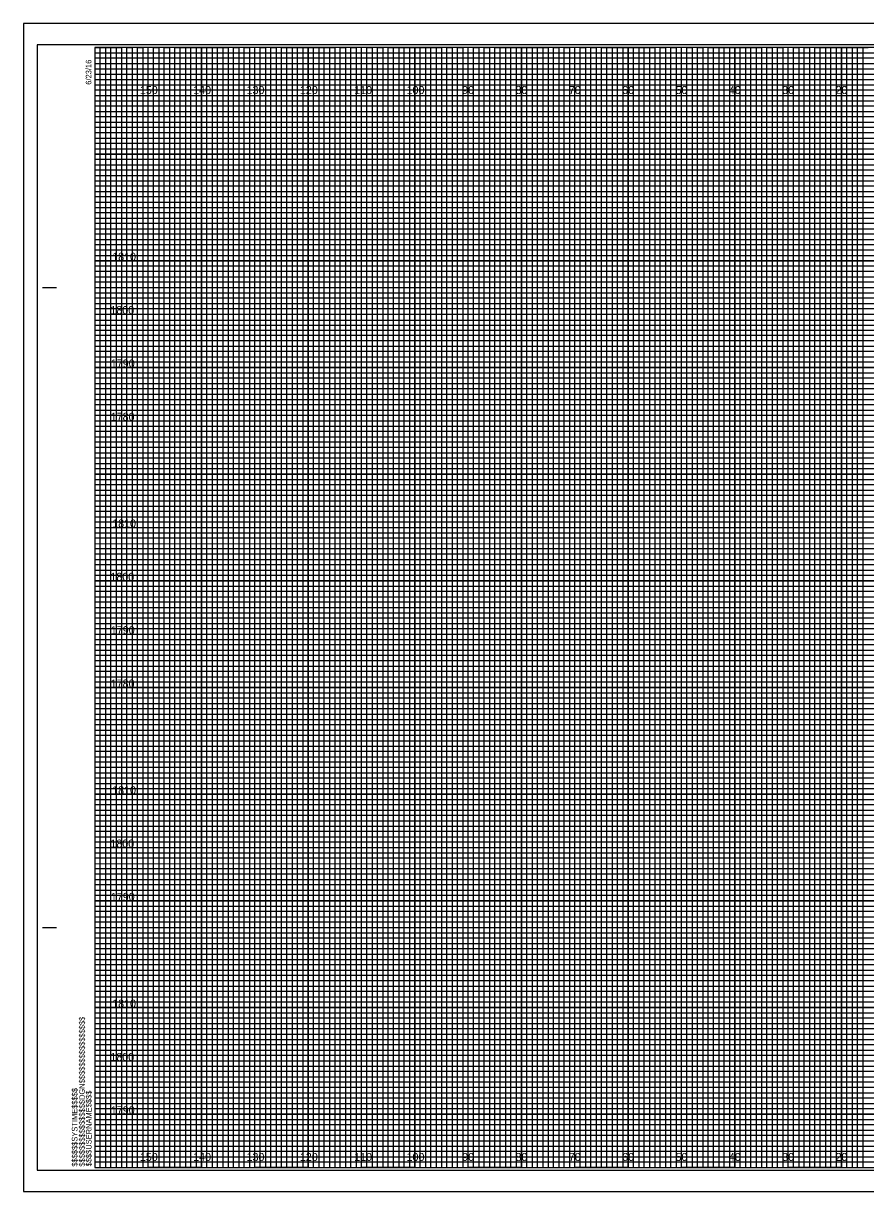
# Model space of a CAD drawing. Extents: x -13 to 323, y -5 to 434.
# Drawn here: x -13.4 to 144.5, y -4.5 to 214.5 of the extents above; entities that cross this region are included whole.
import ezdxf

# ---------------------------------------------------------------- set-up
doc = ezdxf.new("R2010")
doc.units = 0
for name, color, linetype in [('Old_Level_62', 7, 'Continuous'), ('Pattern 1', 7, 'Continuous'), ('Pattern 4', 7, 'Continuous'), ('Pattern 5', 7, 'Continuous'), ('Prop Dimension', 7, 'Continuous'), ('Prop Horizontal Alignment', 7, 'Continuous'), ('Prop PHM Label Text', 7, 'Continuous'), ('Scratch_Level_0', 7, 'Continuous'), ('Scratch_Level_2', 7, 'Continuous'), ('Scratch_Level_3', 7, 'Continuous'), ('Scratch_Level_5', 7, 'Continuous')]:
    doc.layers.add(name, color=color, linetype=linetype)

msp = doc.modelspace()

# ---------------------------------------------------------------- linework, layer by layer
at = {"layer": 'Old_Level_62'}
for p, q in [((0, 209), (260, 209)), ((260, 207.98), (0, 207.98)), ((0, 207.98), (0, 207)), ((0, 207), (260, 207)), ((260, 205.89), (0, 205.89)), ((0, 205.89), (0, 204)), ((0, 204), (320, 204))]:
    msp.add_line(p, q, dxfattribs=at)
for points in [[(0, 203), (270, 203), (320, 203), (320, 202), (0, 202)], [(0, 201), (320, 201), (320, 199), (0, 199)], [(0, 198), (320, 198), (320, 197), (0, 196.98)], [(0, 196), (320, 196), (320, 194), (0, 194)], [(0, 193), (320, 193), (320, 192), (0, 192)], [(0, 191), (320, 191), (320, 189), (0, 189)], [(0, 188), (320, 188), (320, 187), (0, 187)], [(0, 186), (320, 186), (320, 184), (0, 184)], [(0, 183), (320, 183), (320, 182), (0, 182)], [(0, 181), (320, 181), (320, 179), (0, 179)], [(0, 178), (320, 178), (320, 177), (0, 177)], [(0, 176), (320, 176), (320, 173.95), (320, 173), (320, 172), (0, 172)], [(0, 174), (320, 174), (320, 173), (0, 173)], [(0, 171), (320, 171), (320, 169), (0, 169.03)], [(0, 169.03), (320, 169), (320, 168), (0, 168)], [(0, 167), (320, 167), (320, 166), (0, 166)], [(0, 164), (320, 164), (320, 163), (0, 163)], [(0, 162), (320, 162), (320, 161), (0, 161)], [(-0.07, 158.89), (320, 158.89), (320, 157.88), (-0.07, 157.88)], [(0, 157), (320, 157), (320, 156), (0, 156)], [(0, 154), (320, 154), (320, 153), (0, 153)], [(0, 152), (320, 152), (320, 151), (0, 151)], [(0, 149), (320, 149), (320, 148), (0, 148)], [(0, 147), (320, 147), (320, 146), (0, 146)], [(0, 144), (320, 144), (320, 143), (0, 143)], [(0, 142), (320, 142), (320, 141), (0, 141)], [(0, 139), (320, 139), (319.99, 137.98), (0, 138)], [(0, 137), (320, 137), (320, 136), (0, 136)], [(0, 134), (320, 134), (320, 133), (0, 133)], [(0, 132), (320, 132), (320, 131), (0, 131)], [(0, 129), (320, 129), (320, 128), (0, 128)], [(0, 127), (320, 127), (320, 126), (0, 126)], [(0, 124), (320, 124), (320, 123), (0, 123)], [(0, 122), (320, 122), (320, 121), (0, 121)], [(0, 119), (320, 119), (320, 118), (0, 118)], [(0, 116.99), (320.07, 116.91), (320, 116), (0, 116)], [(0, 114), (320, 114), (320, 113), (0, 113)], [(0, 112), (320, 112), (320, 111), (0, 111)], [(0, 109), (320, 109), (320, 108), (0, 108)], [(0, 107), (320, 107), (320, 106), (0, 106)], [(0, 104), (320, 104), (320, 103), (0, 103)], [(0, 102), (320, 102), (320, 101), (0, 101)], [(0, 99), (320, 99), (320, 98), (0, 98)], [(0, 97), (320, 97), (320, 96), (0, 96)], [(0, 94), (320, 94), (320, 93), (0, 93)], [(0, 92), (320, 92), (320, 91), (0, 91)], [(0, 89), (320, 89), (320, 88), (0, 88)], [(0, 87), (320, 87), (320, 86), (0, 86)], [(0, 84), (320, 84), (320, 83), (0, 83)], [(0, 82), (320, 82), (320, 81), (0, 81)], [(0, 79), (320, 79), (319.99, 77.98), (0, 78)], [(0, 77), (320, 77), (320, 76), (0, 76)], [(0, 74), (320, 74), (320, 73), (0, 73)], [(0, 72), (320, 72), (320, 71), (0, 71)], [(0, 69), (320, 69), (320, 68), (0, 68)], [(0, 67), (320, 67), (320, 66), (0, 66)], [(0, 64), (320, 64), (320, 63), (0, 63)], [(0, 62), (320, 62), (320, 61), (0, 61)], [(0, 59), (320, 59), (320, 58), (0, 58)], [(0, 56.99), (320.07, 56.91), (320, 56), (0, 56)], [(0, 54), (320, 54), (320, 53), (0, 53)], [(0, 52), (320, 52), (320, 51), (0, 51)], [(0, 49), (320, 49), (320, 48), (0, 48)], [(0, 47), (320, 47), (320, 46), (0, 46)], [(0, 44), (320, 44), (320, 43), (0, 43)], [(0, 42), (320, 42), (320, 41), (0, 41)], [(0, 39), (320, 39), (320, 38), (0, 38)], [(0, 37), (320, 37), (320, 36), (0, 36)], [(0, 34), (320, 34), (320, 33), (0, 33)], [(0, 32), (320, 32), (320, 31), (0, 31)], [(0, 29), (320, 29), (320, 28), (0, 28)], [(0, 27), (320, 27), (320, 26), (0, 26)], [(0, 24), (320, 24), (320, 23), (0, 23)], [(0, 22), (320, 22), (320, 21), (0, 21)], [(0, 19), (320, 19), (320, 18), (0, 18)], [(0, 17), (320, 17), (320, 16), (0, 16)], [(0, 14), (320, 14), (320, 13), (0, 13)], [(0, 12), (320, 12), (320, 11), (0, 11)], [(0, 9), (320, 9), (320, 8), (0, 8)], [(0, 7), (320, 7), (320, 6), (0, 6)], [(0, 4), (320, 4), (320, 3), (0, 3)], [(0, 2), (320, 2), (320, 1), (0, 1)]]:
    msp.add_lwpolyline(points, dxfattribs=at)
at = {"layer": 'Pattern 1'}
for p, q in [((323.3, 214.5), (-13.4, 214.5)), ((-13.4, 214.5), (-13.4, -4.5)), ((-13.4, -4.5), (323.3, -4.5))]:
    msp.add_line(p, q, dxfattribs=at)
at = {"layer": 'Pattern 4'}
for points in [[(0, 210), (5, 210), (5, 0), (15, 0), (15, 210), (25, 210), (25, 0), (35, 0), (35, 210), (45, 210), (45, 0), (55, 0), (55, 210), (65, 210), (65, 0), (75, 0), (75, 210), (85, 210), (85, 0), (95, 0), (95, 210), (105, 210), (105, 0), (115, 0), (115, 210), (125, 210), (125, 0), (135, 0), (135, 210), (145, 210)], [(0, 205), (275, 205)], [(0, 185), (320, 185), (320, 195), (0, 195)], [(0, 165), (320, 165), (320, 175), (0, 175)], [(0, 145), (320, 145), (320, 155), (0, 155)], [(0, 125), (320, 125), (320, 135), (0, 135)], [(0, 105), (320, 105), (320, 115), (0, 115)], [(0, 85), (320, 85), (320, 95), (0, 95)], [(0, 65), (320, 65), (320, 75), (0, 75)], [(0, 45), (320, 45), (320, 55), (0, 55)], [(0, 25), (320, 25), (320, 35), (0, 35)], [(0, 5), (320, 5), (320, 15), (0, 15)]]:
    msp.add_lwpolyline(points, dxfattribs=at)
at = {"layer": 'Pattern 5'}
for p, q in [((10, 0), (10, 210)), ((20, 0), (20, 210)), ((30, 0), (30, 210)), ((40, 0), (40, 210)), ((50, 0), (50, 210)), ((60, 0), (60, 210)), ((70, 0), (70, 210)), ((80, 0), (80, 210)), ((90, 0), (90, 210)), ((100, 0), (100, 210)), ((110, 0), (110, 210)), ((120, 0), (120, 210)), ((130, 0), (130, 210)), ((140, 0), (140, 210)), ((0, 200), (320, 200)), ((0, 190), (320, 190)), ((0, 180), (320, 180)), ((0, 170), (320, 170)), ((0, 160), (320, 160)), ((0, 150), (320, 150)), ((0, 140), (320, 140)), ((0, 130), (320, 130)), ((0, 120), (320, 120)), ((0, 110), (320, 110)), ((0, 100), (320, 100)), ((0, 90), (320, 90)), ((0, 80), (320, 80)), ((0, 70), (320, 70)), ((0, 60), (320, 60)), ((0, 50), (320, 50)), ((0, 40), (320, 40)), ((0, 30), (320, 30)), ((0, 20), (320, 20)), ((0, 10), (320, 10))]:
    msp.add_line(p, q, dxfattribs=at)
at = {"layer": 'Prop Dimension'}
for p, q in [((-9.8, 165), (-7.3, 165)), ((-9.7, 165), (-7.2, 165)), ((-9.8, 45), (-7.3, 45)), ((-9.7, 45), (-7.2, 45)), ((0, 0), (0, 0)), ((0, 0), (0, 0)), ((0, 0), (0, 0)), ((0, 0), (0, 0)), ((0, 0), (0, 0)), ((0, 0), (0, 0)), ((0, 0), (0, 0))]:
    msp.add_line(p, q, dxfattribs=at)
msp.add_lwpolyline([(320, 210), (0, 210), (0, 0), (320, 0)], close=True, dxfattribs=at)
at = {"layer": 'Prop Horizontal Alignment'}
for p, q in [((10, 210), (0, 210)), ((10, 0), (10, 210)), ((30, 210), (20, 210)), ((20, 210), (20, 0)), ((30, 0), (30, 210)), ((50, 210), (40, 210)), ((40, 210), (40, 0)), ((50, 0), (50, 210)), ((70, 210), (60, 210)), ((60, 210), (60, 0)), ((70, 0), (70, 210)), ((90, 210), (80, 210)), ((80, 210), (80, 0)), ((90, 0), (90, 210)), ((110, 210), (100, 210)), ((100, 210), (100, 0)), ((110, 0), (110, 210)), ((130, 210), (120, 210)), ((120, 210), (120, 0)), ((130, 0), (130, 210)), ((150, 210), (140, 210)), ((140, 210), (140, 0)), ((20, 0), (10, 0)), ((40, 0), (30, 0)), ((60, 0), (50, 0)), ((80, 0), (70, 0)), ((100, 0), (90, 0)), ((120, 0), (110, 0)), ((140, 0), (130, 0))]:
    msp.add_line(p, q, dxfattribs=at)
for points in [[(0, 200), (320, 200), (320, 190), (0, 190)], [(0, 180), (320, 180), (320, 170), (0, 170)], [(0, 160), (320, 160), (320, 150), (0, 150)], [(0, 140), (320, 140), (320, 130), (0, 130)], [(0, 120), (320, 120), (320, 110), (0, 110)], [(0, 100), (320, 100), (320, 90), (0, 90)], [(0, 80), (320, 80), (320, 70), (0, 70)], [(0, 60), (320, 60), (320, 50), (0, 50)], [(0, 40), (320, 40), (320, 30), (0, 30)], [(0, 20), (320, 20), (320, 10), (0, 10)]]:
    msp.add_lwpolyline(points, dxfattribs=at)
at = {"layer": 'Prop PHM Label Text'}
for points in [[(0, 0), (1, 0), (1, 210), (2, 210), (2, 0)], [(2, 0), (3, 0), (3, 210), (4, 210), (4, 0)], [(5, 0), (6, 0), (6, 210), (7, 210), (7, 0)], [(7, 0), (8, 0), (8, 210), (9, 210), (9, 0)], [(10, 0), (11, 0), (11, 210), (12, 210), (12, 0)], [(12, 0), (13, 0), (13, 210), (14, 210), (14, 0)], [(15, 0), (16, 0), (16, 210), (17, 210), (17, 0)], [(17, 0), (18, 0), (18, 210), (19, 210), (19, 0)], [(20, 0), (21, 0), (21, 210), (22, 210), (22, 0)], [(22, 0), (23, 0), (23, 210), (24, 210), (24, 0)], [(25, 0), (26, 0), (26, 210), (27, 210), (27, 0)], [(27, 0), (28, 0), (28, 210), (29, 210), (29, 0)], [(30, 0), (31, 0), (31, 210), (32, 210), (32, 0)], [(32, 0), (33, 0), (33, 210), (34, 210), (34, 0)], [(35, 0), (36, 0), (36, 210), (37, 210), (37, 0)], [(37, 0), (38, 0), (38, 210), (39, 210), (39, 0)], [(40, 0), (41, 0), (41, 210), (42, 210), (42, 0)], [(42, 0), (43, 0), (43, 210), (44, 210), (44, 0)], [(45, 0), (46, 0), (46, 210), (47, 210), (47, 0)], [(47, 0), (48, 0), (48, 210), (49, 210), (49, 0)], [(50, 0), (51, 0), (51, 210), (52, 210), (52, 0)], [(52, 0), (53, 0), (53, 210), (54, 210), (54, 0)], [(55, 0), (56, 0), (56, 210), (57, 210), (57, 0)], [(57, 0), (58, 0), (58, 210), (59, 210), (59, 0)], [(60, 0), (61, 0), (61, 210), (62, 210), (62, 0)], [(62, 0), (63, 0), (63, 210), (64, 210), (64, 0)], [(65, 0), (66, 0), (66, 210), (67, 210), (67, 0)], [(67, 0), (68, 0), (68, 210), (69, 210), (69, 0)], [(70, 0), (71, 0), (71, 210), (72, 210), (72, 0)], [(72, 0), (73, 0), (73, 210), (74, 210), (74, 0)], [(75, 0), (76, 0), (76, 210), (77, 210), (77, 0)], [(77, 0), (78, 0), (78, 210), (79, 210), (79, 0)], [(80, 0), (81, 0), (81, 210), (82, 210), (82, 0)], [(82, 0), (83, 0), (83, 210), (84, 210), (84, 0)], [(85, 0), (86, 0), (86, 210), (87, 210), (87, 0)], [(87, 0), (88, 0), (88, 210), (89, 210), (89, 0)], [(90, 0), (91, 0), (91, 210), (92, 210), (92, 0)], [(92, 0), (93, 0), (93, 210), (94, 210), (94, 0)], [(95, 0), (96, 0), (96, 210), (97, 210), (97, 0)], [(97, 0), (98, 0), (98, 210), (99, 210), (99, 0)], [(100, 0), (101, 0), (101, 210), (102, 210), (102, 0)], [(102, 0), (103, 0), (103, 210), (104, 210), (104, 0)], [(105, 0), (106, 0), (106, 210), (107, 210), (107, 0)], [(107, 0), (108, 0), (108, 210), (109, 210), (109, 0)], [(110, 0), (111, 0), (111, 210), (112, 210), (112, 0)], [(112, 0), (113, 0), (113, 210), (114, 210), (114, 0)], [(115, 0), (116, 0), (116, 210), (117, 210), (117, 0)], [(117, 0), (118, 0), (118, 210), (119, 210), (119, 0)], [(120, 0), (121, 0), (121, 210), (122, 210), (122, 0)], [(122, 0), (123, 0), (123, 210), (124, 210), (124, 0)], [(125, 0), (126, 0), (126, 210), (127, 210), (127, 0)], [(127, 0), (128, 0), (128, 210), (129, 210), (129, 0)], [(130, 0), (131, 0), (131, 210), (132, 210), (132, 0)], [(132, 0), (133, 0), (133, 210), (134, 210), (134, 0)], [(135, 0), (136, 0), (136, 210), (137, 210), (137, 0)], [(137, 0), (138, 0), (138, 210), (139, 210), (139, 0)], [(140, 0), (141, 0), (141, 210), (142, 210), (142, 0)], [(142, 0), (143, 0), (143, 210), (144, 210), (144, 0)]]:
    msp.add_lwpolyline(points, dxfattribs=at)
at = {"layer": 'Scratch_Level_0'}
msp.add_lwpolyline([(-10.8, -0.5), (322.4, -0.5), (322.4, 210.5), (-10.8, 210.5)], close=True, dxfattribs=at)
at = {"layer": 'Scratch_Level_5'}
msp.add_lwpolyline([(-13.4, -4.5), (323.3, -4.5), (323.3, 214.5), (-13.4, 214.5)], close=True, dxfattribs=at)

# ---------------------------------------------------------------- texts
at = {"layer": 'Prop Dimension'}
for s, p in [('6/23/16', (-0.65, 203)), ('$$$$$$$$$$$$$$$$DGN$$$$$$$$$$$$$$$$', (-1.88, 0.18)), ('$$$$$$SYSTIME$$$$$', (-3.26, 0.18)), ('$$$$USERNAME$$$$', (-0.62, 0.23))]:
    msp.add_text(s, height=1.05, rotation=90, dxfattribs=at).set_placement(p)
at = {"layer": 'Scratch_Level_2'}
for s, p in [('1810', (3.25, 170)), ('1800', (2.92, 160)), ('1790', (3, 150)), ('1780', (2.98, 140)), ('1810', (3.25, 120)), ('1800', (2.92, 110)), ('1790', (3, 100)), ('1780', (2.98, 90)), ('1810', (3.25, 70)), ('1800', (2.92, 60)), ('1790', (3, 50)), ('1810', (3.25, 30)), ('1800', (2.92, 20)), ('1790', (3, 10))]:
    msp.add_text(s, height=1.5, dxfattribs=at).set_placement(p)
at = {"layer": 'Scratch_Level_3'}
for s, p in [('150', (8.44, 201.25)), ('140', (18.44, 201.25)), ('130', (28.44, 201.25)), ('120', (38.44, 201.25)), ('110', (48.62, 201.25)), ('100', (58.44, 201.25)), ('90', (68.86, 201.25)), ('80', (78.86, 201.25)), ('70', (88.86, 201.25)), ('60', (98.86, 201.25)), ('50', (108.86, 201.25)), ('40', (118.86, 201.25)), ('30', (128.86, 201.25)), ('20', (138.86, 201.25)), ('150', (8.44, 1.25)), ('140', (18.44, 1.25)), ('130', (28.44, 1.25)), ('120', (38.44, 1.25)), ('110', (48.62, 1.25)), ('100', (58.44, 1.25)), ('90', (68.86, 1.25)), ('80', (78.86, 1.25)), ('70', (88.86, 1.25)), ('60', (98.86, 1.25)), ('50', (108.86, 1.25)), ('40', (118.86, 1.25)), ('30', (128.86, 1.25)), ('20', (138.86, 1.25))]:
    msp.add_text(s, height=1.5, dxfattribs=at).set_placement(p)

doc.saveas('drawing.dxf')
